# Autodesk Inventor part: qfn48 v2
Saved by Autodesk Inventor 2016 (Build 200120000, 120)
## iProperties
Created: 2016-09
Part Number: qfn48 v2
Material: Generic
Document SubType Name: Modeling
Designer: Administrator
Appearance: Generic
Author: Administrator
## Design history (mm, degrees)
feature "Body1"
feature "Body64"
feature "Body65"
feature "Body66"
feature "Body67"
feature "Body68"
feature "Body69"
feature "Body70"
feature "Body71"
feature "Body72"
feature "Body73"
feature "Body74"
feature "Body75"
feature "Body109"
feature "Body110"
feature "Body111"
feature "Body106"
feature "Body107"
feature "Body108"
feature "Body97"
feature "Body98"
feature "Body99"
feature "Body94"
feature "Body95"
feature "Body96"
feature "Body88"
feature "Body89"
feature "Body90"
feature "Body100"
feature "Body101"
feature "Body102"
feature "Body91"
feature "Body92"
feature "Body93"
feature "Body103"
feature "Body104"
feature "Body105"
feature "Body85"
feature "Body86"
feature "Body87"
feature "Body76"
feature "Body77"
feature "Body78"
feature "Body79"
feature "Body80"
feature "Body81"
feature "Body82"
feature "Body83"
feature "Body84"
body "Solid1"
body "Solid2"
body "Solid3"
body "Solid4"
body "Solid5"
body "Solid6"
body "Solid7"
body "Solid8"
body "Solid9"
body "Solid10"
body "Solid11"
body "Solid12"
body "Solid13"
body "Solid14"
body "Solid15"
body "Solid16"
body "Solid17"
body "Solid18"
body "Solid19"
body "Solid20"
body "Solid21"
body "Solid22"
body "Solid23"
body "Solid24"
body "Solid25"
body "Solid26"
body "Solid27"
body "Solid28"
body "Solid29"
body "Solid30"
body "Solid31"
body "Solid32"
body "Solid33"
body "Solid34"
body "Solid35"
body "Solid36"
body "Solid37"
body "Solid38"
body "Solid39"
body "Solid40"
body "Solid41"
body "Solid42"
body "Solid43"
body "Solid44"
body "Solid45"
body "Solid46"
body "Solid47"
body "Solid48"
body "Solid49"
